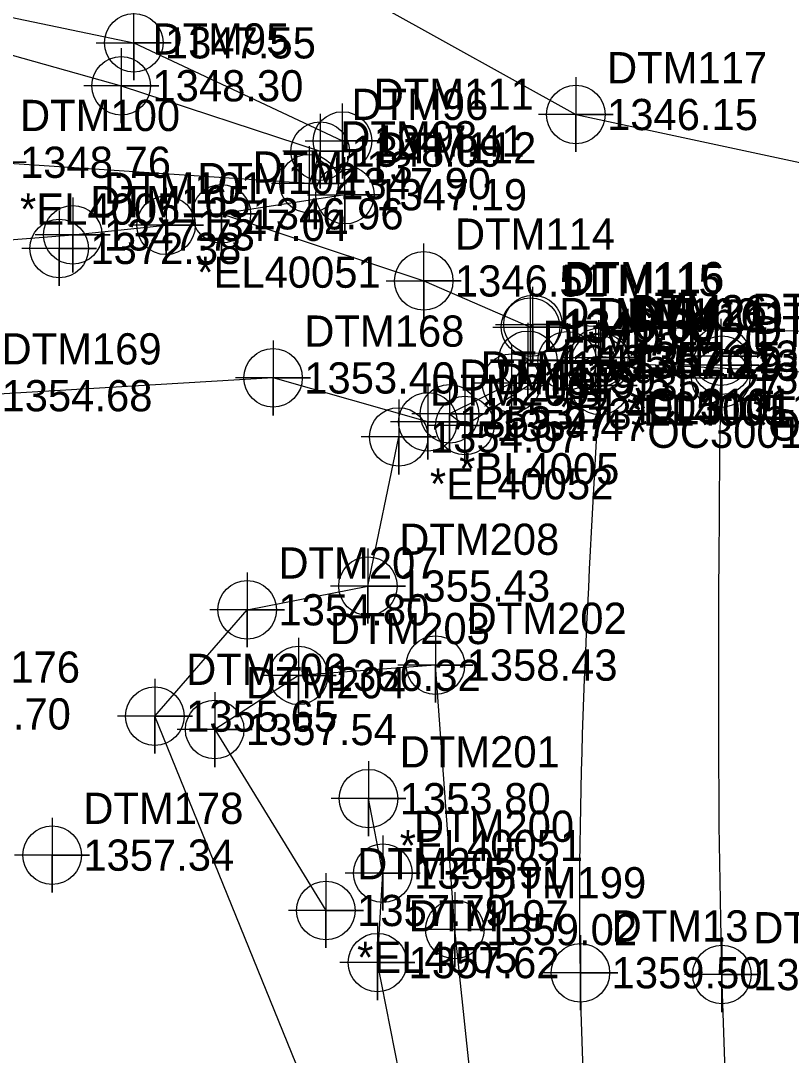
# Model space of a CAD drawing. Extents: x 1251905 to 1252853, y 859795 to 860170.
# Drawn here: x 1251978.6 to 1252040.3, y 859945.7 to 860028.5 of the extents above; entities that cross this region are included whole.
import ezdxf

# ---------------------------------------------------------------- set-up
doc = ezdxf.new("R2010")
doc.units = 0
for name, color, linetype in [('Exist DTM Breakline', 7, 'Continuous'), ('Exist DTM Breakline Cogo Comment', 7, 'Continuous'), ('Exist DTM Breakline Cogo Elevation', 7, 'Continuous'), ('Exist DTM Breakline Cogo Number', 7, 'Continuous'), ('Exist DTM Breakline Cogo Point CELL', 7, 'Continuous'), ('Exist DTM Breakline Underwater', 7, 'Continuous'), ('Exist DTM Breakline Underwater Cogo Elevation', 7, 'Continuous'), ('Exist DTM Breakline Underwater Cogo Number', 7, 'Continuous'), ('Exist DTM Breakline Underwater Cogo Point CELL', 7, 'Continuous'), ('Exist DTM Crownline', 7, 'Continuous'), ('Exist DTM Crownline Cogo Comment', 7, 'Continuous'), ('Exist DTM Crownline Cogo Elevation', 7, 'Continuous'), ('Exist DTM Crownline Cogo Number', 7, 'Continuous'), ('Exist DTM Crownline Cogo Point CELL', 7, 'Continuous'), ('Exist DTM Regular Point CELL', 7, 'Continuous'), ('Exist DTM Regular Point Cogo Elevation', 7, 'Continuous'), ('Exist DTM Regular Point Cogo Number', 7, 'Continuous'), ('Exist Hydro Stream or Body of Water', 7, 'Continuous'), ('Exist Hydro Stream or Body of Water Cogo Elevation', 7, 'Continuous'), ('Exist Hydro Stream or Body of Water Cogo Number', 7, 'Continuous'), ('Exist Hydro Stream or Body of Water Cogo Point CELL', 7, 'Continuous'), ('Exist Roads EOP', 7, 'Continuous'), ('Exist Roads EOP Cogo Comment', 7, 'Continuous'), ('Exist Roads EOP Cogo Elevation', 7, 'Continuous'), ('Exist Roads EOP Cogo Number', 7, 'Continuous'), ('Exist Roads EOP Cogo Point CELL', 7, 'Continuous'), ('Exist Structure Major Deck Tunnel Box Culvert Cogo Comment', 7, 'Continuous'), ('Exist Structure Major Deck Tunnel Box Culvert Cogo Elevation', 7, 'Continuous'), ('Exist Structure Major Deck Tunnel Box Culvert Cogo Number', 7, 'Continuous'), ('Exist Structure Major Deck Tunnel Box Culvert Cogo Point CELL', 7, 'Continuous'), ('Exist Utilities Power UG Cable Cogo Elevation', 7, 'Continuous'), ('Exist Utilities Power UG Cable Cogo Number', 7, 'Continuous'), ('Exist Utilities Power UG Cable Cogo Point CELL', 7, 'Continuous')]:
    doc.layers.add(name, color=color, linetype=linetype)

msp = doc.modelspace()

# ---------------------------------------------------------------- linework, layer by layer
at = {"layer": 'Exist DTM Breakline'}
for points in [[(1251922.639, 860029.05), (1251957.547, 860031.512), (1251986.698, 860023.305), (1252002.628, 860018.068), (1252001.734, 860015.469), (1251976.094, 860017.179)], [(1251919.208, 860016.218), (1251952.017, 860008.928), (1251982.813, 860011.362), (1251990.283, 860012.128)], [(1252011.253, 859996.384), (1251998.853, 859999.907), (1251974.611, 859998.485), (1251951.238, 860003.66), (1251927.383, 860002.484), (1251907.913, 860010.701)], [(1252019.258, 860001.319), (1252017.94, 859999.494), (1252012.977, 859997.038), (1252014.204, 859996.093), (1252022.404, 860001.28), (1252024.677, 860001.074)], [(1252011.684, 859917.958), (1251989.391, 859972.821), (1251996.782, 859981.337), (1252006.454, 859983.238), (1252008.913, 859995.179)], [(1252032.55, 859801.96), (1252026.376, 859850.562), (1252019.584, 859901.847), (1252017.298, 859918.826), (1252013.415, 859955.727), (1252011.851, 859976.908), (1252000.895, 859976.087), (1251994.179, 859971.747), (1252003.085, 859957.255)], [(1252030.055, 859801.697), (1252023.898, 859850.26), (1252016.404, 859902.034), (1252014.144, 859917.861), (1252007.209, 859953.081), (1252007.638, 859960.249), (1252006.494, 859966.213)]]:
    msp.add_lwpolyline(points, dxfattribs=at)
at = {"layer": 'Exist DTM Breakline Cogo Point CELL'}
for points in [[(1251986.698, 860026.305), (1251986.698, 860020.305), (1251986.698, 860023.305), (1251989.698, 860023.305), (1251983.698, 860023.305)], [(1252002.628, 860021.068), (1252002.628, 860015.068), (1252002.628, 860018.068), (1252005.628, 860018.068), (1251999.628, 860018.068)], [(1251976.094, 860020.179), (1251976.094, 860014.179), (1251976.094, 860017.179), (1251979.094, 860017.179), (1251973.094, 860017.179)], [(1252001.734, 860018.469), (1252001.734, 860012.469), (1252001.734, 860015.469), (1252004.734, 860015.469), (1251998.734, 860015.469)], [(1251990.283, 860015.128), (1251990.283, 860009.128), (1251990.283, 860012.128), (1251993.283, 860012.128), (1251987.283, 860012.128)], [(1251982.813, 860014.362), (1251982.813, 860008.362), (1251982.813, 860011.362), (1251985.813, 860011.362), (1251979.813, 860011.362)], [(1252019.258, 860004.319), (1252019.258, 859998.319), (1252019.258, 860001.319), (1252022.258, 860001.319), (1252016.258, 860001.319)], [(1252022.404, 860004.28), (1252022.404, 859998.28), (1252022.404, 860001.28), (1252025.404, 860001.28), (1252019.404, 860001.28)], [(1252024.677, 860004.074), (1252024.677, 859998.074), (1252024.677, 860001.074), (1252027.677, 860001.074), (1252021.677, 860001.074)], [(1251998.853, 860002.907), (1251998.853, 859996.907), (1251998.853, 859999.907), (1252001.853, 859999.907), (1251995.853, 859999.907)], [(1252017.94, 860002.494), (1252017.94, 859996.494), (1252017.94, 859999.494), (1252020.94, 859999.494), (1252014.94, 859999.494)], [(1252011.253, 859999.384), (1252011.253, 859993.384), (1252011.253, 859996.384), (1252014.253, 859996.384), (1252008.253, 859996.384)], [(1252012.977, 860000.038), (1252012.977, 859994.038), (1252012.977, 859997.038), (1252015.977, 859997.038), (1252009.977, 859997.038)], [(1252014.204, 859999.093), (1252014.204, 859993.093), (1252014.204, 859996.093), (1252017.204, 859996.093), (1252011.204, 859996.093)], [(1252008.913, 859998.179), (1252008.913, 859992.179), (1252008.913, 859995.179), (1252011.913, 859995.179), (1252005.913, 859995.179)], [(1252006.454, 859986.238), (1252006.454, 859980.238), (1252006.454, 859983.238), (1252009.454, 859983.238), (1252003.454, 859983.238)], [(1251996.782, 859984.337), (1251996.782, 859978.337), (1251996.782, 859981.337), (1251999.782, 859981.337), (1251993.782, 859981.337)], [(1252011.851, 859979.908), (1252011.851, 859973.908), (1252011.851, 859976.908), (1252014.851, 859976.908), (1252008.851, 859976.908)], [(1252000.895, 859979.087), (1252000.895, 859973.087), (1252000.895, 859976.087), (1252003.895, 859976.087), (1251997.895, 859976.087)], [(1251989.391, 859975.821), (1251989.391, 859969.821), (1251989.391, 859972.821), (1251992.391, 859972.821), (1251986.391, 859972.821)], [(1251994.179, 859974.747), (1251994.179, 859968.747), (1251994.179, 859971.747), (1251997.179, 859971.747), (1251991.179, 859971.747)], [(1252006.494, 859969.213), (1252006.494, 859963.213), (1252006.494, 859966.213), (1252009.494, 859966.213), (1252003.494, 859966.213)], [(1252007.638, 859963.249), (1252007.638, 859957.249), (1252007.638, 859960.249), (1252010.638, 859960.249), (1252004.638, 859960.249)], [(1252003.085, 859960.255), (1252003.085, 859954.255), (1252003.085, 859957.255), (1252006.085, 859957.255), (1252000.085, 859957.255)], [(1252013.415, 859958.727), (1252013.415, 859952.727), (1252013.415, 859955.727), (1252016.415, 859955.727), (1252010.415, 859955.727)], [(1252007.209, 859956.081), (1252007.209, 859950.081), (1252007.209, 859953.081), (1252010.209, 859953.081), (1252004.209, 859953.081)]]:
    msp.add_lwpolyline(points, dxfattribs=at)
for centre in [(1251986.698, 860023.305), (1252002.628, 860018.068), (1252001.734, 860015.469), (1251990.283, 860012.128), (1251982.813, 860011.362), (1252019.258, 860001.319), (1252022.404, 860001.28), (1252024.677, 860001.074), (1251998.853, 859999.907), (1252017.94, 859999.494), (1252012.977, 859997.038), (1252011.253, 859996.384), (1252014.204, 859996.093), (1252008.913, 859995.179), (1252006.454, 859983.238), (1251996.782, 859981.337), (1252011.851, 859976.908), (1252000.895, 859976.087), (1251989.391, 859972.821), (1251994.179, 859971.747), (1252006.494, 859966.213), (1252007.638, 859960.249), (1252003.085, 859957.255), (1252013.415, 859955.727), (1252007.209, 859953.081)]:
    msp.add_circle(centre, 2.344, dxfattribs=at)
at = {"layer": 'Exist DTM Breakline Underwater'}
msp.add_lwpolyline([(1251927.42, 860049.663), (1251960.607, 860043.428), (1251991.544, 860038.543), (1252023.095, 860021.002), (1252051.108, 860015.006), (1252097.444, 860018.35), (1252136.124, 860025.415), (1252179.795, 860024.836), (1252209.042, 860015.729)], dxfattribs=at)
at = {"layer": 'Exist DTM Breakline Underwater Cogo Point CELL'}
msp.add_lwpolyline([(1252023.095, 860024.002), (1252023.095, 860018.002), (1252023.095, 860021.002), (1252026.095, 860021.002), (1252020.095, 860021.002)], dxfattribs=at)
msp.add_circle((1252023.095, 860021.002), 2.344, dxfattribs=at)
at = {"layer": 'Exist DTM Crownline'}
msp.add_line((1252034.696, 859999.877), (1252034.747, 860000.476), dxfattribs=at)
msp.add_spline([(1252046.752, 859804.377), (1252041.79, 859852.778), (1252037.509, 859902.564), (1252034.798, 859952.124), (1252034.696, 859999.877)], degree=3, dxfattribs=at)
at = {"layer": 'Exist DTM Crownline Cogo Point CELL'}
for points in [[(1252034.785, 860003.924), (1252034.785, 859997.924), (1252034.785, 860000.924), (1252037.785, 860000.924), (1252031.785, 860000.924)], [(1252034.696, 860002.877), (1252034.696, 859996.877), (1252034.696, 859999.877), (1252037.696, 859999.877), (1252031.696, 859999.877)], [(1252034.798, 859955.124), (1252034.798, 859949.124), (1252034.798, 859952.124), (1252037.798, 859952.124), (1252031.798, 859952.124)]]:
    msp.add_lwpolyline(points, dxfattribs=at)
for centre in [(1252034.785, 860000.924), (1252034.696, 859999.877), (1252034.798, 859952.124)]:
    msp.add_circle(centre, 2.344, dxfattribs=at)
at = {"layer": 'Exist DTM Regular Point CELL'}
for points in [[(1252034.708, 860004.651), (1252034.708, 859998.651), (1252034.708, 860001.651), (1252037.708, 860001.651), (1252031.708, 860001.651)], [(1251981.162, 859964.689), (1251981.162, 859958.689), (1251981.162, 859961.689), (1251984.162, 859961.689), (1251978.162, 859961.689)]]:
    msp.add_lwpolyline(points, dxfattribs=at)
for centre in [(1252034.708, 860001.651), (1251981.162, 859961.689)]:
    msp.add_circle(centre, 2.344, dxfattribs=at)
at = {"layer": 'Exist Hydro Stream or Body of Water'}
msp.add_lwpolyline([(1251923.519, 860032.492), (1251957.999, 860032.964), (1251987.699, 860026.743), (1252004.412, 860018.883), (1252004.612, 860014.582), (1251994.716, 860013.049), (1252010.915, 860007.676), (1252019.462, 860003.97), (1252019.665, 860004.195), (1252046.38, 860003.539), (1252090.782, 859996.797), (1252140.715, 860010.791), (1252179.759, 860006.581), (1252205.549, 860000.12)], dxfattribs=at)
at = {"layer": 'Exist Hydro Stream or Body of Water Cogo Point CELL'}
for points in [[(1251984.699, 860026.743), (1251990.699, 860026.743), (1251987.699, 860026.743), (1251987.699, 860023.743), (1251987.699, 860029.743)], [(1252001.412, 860018.883), (1252007.412, 860018.883), (1252004.412, 860018.883), (1252004.412, 860015.883), (1252004.412, 860021.883)], [(1252001.612, 860014.582), (1252007.612, 860014.582), (1252004.612, 860014.582), (1252004.612, 860011.582), (1252004.612, 860017.582)], [(1251991.716, 860013.049), (1251997.716, 860013.049), (1251994.716, 860013.049), (1251994.716, 860010.049), (1251994.716, 860016.049)], [(1252007.915, 860007.676), (1252013.915, 860007.676), (1252010.915, 860007.676), (1252010.915, 860004.676), (1252010.915, 860010.676)], [(1252016.462, 860003.97), (1252022.462, 860003.97), (1252019.462, 860003.97), (1252019.462, 860000.97), (1252019.462, 860006.97)], [(1252016.665, 860004.195), (1252022.665, 860004.195), (1252019.665, 860004.195), (1252019.665, 860001.195), (1252019.665, 860007.195)]]:
    msp.add_lwpolyline(points, dxfattribs=at)
for centre in [(1251987.699, 860026.743), (1252004.412, 860018.883), (1252004.612, 860014.582), (1251994.716, 860013.049), (1252010.915, 860007.676), (1252019.462, 860003.97), (1252019.665, 860004.195)]:
    msp.add_circle(centre, 2.344, dxfattribs=at)
at = {"layer": 'Exist Roads EOP'}
msp.add_line((1252025.019, 859999.306), (1252025.059, 860001.178), dxfattribs=at)
msp.add_lwpolyline([(1252025.059, 860001.178), (1252043.922, 860000.266)], dxfattribs=at)
msp.add_spline([(1252037.3, 859803.862), (1252031.99, 859851.603), (1252026.974, 859902.147), (1252023.461, 859952.269), (1252025.019, 859999.306)], degree=3, dxfattribs=at)
at = {"layer": 'Exist Roads EOP Cogo Point CELL'}
for points in [[(1252025.059, 860004.178), (1252025.059, 859998.178), (1252025.059, 860001.178), (1252028.059, 860001.178), (1252022.059, 860001.178)], [(1252025.019, 860002.306), (1252025.019, 859996.306), (1252025.019, 859999.306), (1252028.019, 859999.306), (1252022.019, 859999.306)], [(1252023.461, 859955.269), (1252023.461, 859949.269), (1252023.461, 859952.269), (1252026.461, 859952.269), (1252020.461, 859952.269)]]:
    msp.add_lwpolyline(points, dxfattribs=at)
for centre in [(1252025.059, 860001.178), (1252025.019, 859999.306), (1252023.461, 859952.269)]:
    msp.add_circle(centre, 2.344, dxfattribs=at)
at = {"layer": 'Exist Structure Major Deck Tunnel Box Culvert Cogo Point CELL'}
msp.add_lwpolyline([(1252021.949, 860001.546), (1252027.949, 860001.546), (1252024.949, 860001.546), (1252024.949, 860004.546), (1252024.949, 859998.546)], dxfattribs=at)
msp.add_circle((1252024.949, 860001.546), 2.344, dxfattribs=at)
at = {"layer": 'Exist Utilities Power UG Cable Cogo Point CELL'}
msp.add_lwpolyline([(1251981.728, 860013.279), (1251981.728, 860007.279), (1251981.728, 860010.279), (1251984.728, 860010.279), (1251978.728, 860010.279)], dxfattribs=at)
msp.add_circle((1251981.728, 860010.279), 2.344, dxfattribs=at)

# ---------------------------------------------------------------- texts
at = {"layer": 'Exist DTM Breakline Cogo Comment'}
for s, p in [('*EL4005', (1251978.594, 860012.179)), ('*EL40051', (1251992.783, 860007.128)), ('*BL4005', (1252021.758, 859996.319)), ('*EL4005', (1252027.177, 859996.074)), ('*BL4005', (1252013.753, 859991.384)), ('*EL40052', (1252011.413, 859990.179)), ('*EL40051', (1252008.994, 859961.213)), ('*EL4005', (1252005.585, 859952.255))]:
    msp.add_text(s, height=2.5, dxfattribs=at).set_placement(p)
at = {"layer": 'Exist DTM Breakline Cogo Elevation'}
for s, p in [('1348.30', (1251989.198, 860022.055)), ('1348.09', (1252005.128, 860016.818)), ('1348.76', (1251978.594, 860015.929)), ('1347.90', (1252004.234, 860014.219)), ('1347.04', (1251992.783, 860010.878)), ('1347.73', (1251985.313, 860010.112)), ('1347.91', (1252021.758, 860000.069)), ('1357.20', (1252024.904, 860000.03)), ('1357.27', (1252027.177, 859999.824)), ('1353.40', (1252001.353, 859998.657)), ('1349.51', (1252020.44, 859998.244)), ('1354.68', (1251977.111, 859997.235)), ('1353.97', (1252013.753, 859995.134)), ('1353.73', (1252015.477, 859995.788)), ('1354.47', (1252016.704, 859994.843)), ('1354.07', (1252011.413, 859993.929)), ('1355.43', (1252008.954, 859981.988)), ('1354.80', (1251999.282, 859980.087)), ('1358.43', (1252014.351, 859975.658)), ('1356.32', (1252003.395, 859974.837)), ('1355.65', (1251991.891, 859971.571)), ('1357.54', (1251996.679, 859970.497)), ('1353.80', (1252008.994, 859964.963)), ('1355.91', (1252010.138, 859958.999)), ('1357.79', (1252005.585, 859956.005)), ('1359.02', (1252015.915, 859954.477)), ('1357.62', (1252009.709, 859951.831))]:
    msp.add_text(s, height=2.5, dxfattribs=at).set_placement(p)
at = {"layer": 'Exist DTM Breakline Cogo Number'}
for s, p in [('DTM95', (1251989.198, 860025.805)), ('DTM96', (1252005.128, 860020.568)), ('DTM100', (1251978.594, 860019.679)), ('DTM98', (1252004.234, 860017.969)), ('DTM102', (1251992.783, 860014.628)), ('DTM101', (1251985.313, 860013.862)), ('DTM154', (1252021.758, 860003.819)), ('DTM160', (1252024.904, 860003.78)), ('DTM161', (1252027.177, 860003.574)), ('DTM168', (1252001.353, 860002.407)), ('DTM155', (1252020.44, 860001.994)), ('DTM169', (1251977.111, 860000.985)), ('DTM158', (1252015.477, 859999.538)), ('DTM167', (1252013.753, 859998.884)), ('DTM159', (1252016.704, 859998.593)), ('DTM209', (1252011.413, 859997.679)), ('DTM208', (1252008.954, 859985.738)), ('DTM207', (1251999.282, 859983.837)), ('DTM202', (1252014.351, 859979.408)), ('DTM203', (1252003.395, 859978.587)), ('DTM206', (1251991.891, 859975.321)), ('DTM204', (1251996.679, 859974.247)), ('DTM201', (1252008.994, 859968.713)), ('DTM200', (1252010.138, 859962.749)), ('DTM205', (1252005.585, 859959.755)), ('DTM199', (1252015.915, 859958.227)), ('DTM197', (1252009.709, 859955.581))]:
    msp.add_text(s, height=2.5, dxfattribs=at).set_placement(p)
at = {"layer": 'Exist DTM Breakline Underwater Cogo Elevation'}
msp.add_text('1346.15', height=2.5, dxfattribs=at).set_placement((1252025.595, 860019.752))
at = {"layer": 'Exist DTM Breakline Underwater Cogo Number'}
msp.add_text('DTM117', height=2.5, dxfattribs=at).set_placement((1252025.595, 860023.502))
at = {"layer": 'Exist DTM Crownline Cogo Comment'}
for s, p in [('*EL3008', (1252037.285, 859995.924)), ('*OC3008', (1252037.196, 859994.877))]:
    msp.add_text(s, height=2.5, dxfattribs=at).set_placement(p)
at = {"layer": 'Exist DTM Crownline Cogo Elevation'}
for s, p in [('1357.30', (1252037.285, 859999.674)), ('1357.33', (1252037.196, 859998.627)), ('1359.55', (1252037.298, 859950.874))]:
    msp.add_text(s, height=2.5, dxfattribs=at).set_placement(p)
at = {"layer": 'Exist DTM Crownline Cogo Number'}
for s, p in [('DTM19', (1252037.285, 860003.424)), ('DTM18', (1252037.196, 860002.377)), ('DTM14', (1252037.298, 859954.624))]:
    msp.add_text(s, height=2.5, dxfattribs=at).set_placement(p)
at = {"layer": 'Exist DTM Regular Point Cogo Elevation'}
for s, p in [('1357.30', (1252037.208, 860000.401)), ('1358.70', (1251970.579, 859971.749)), ('1357.34', (1251983.662, 859960.439))]:
    msp.add_text(s, height=2.5, dxfattribs=at).set_placement(p)
at = {"layer": 'Exist DTM Regular Point Cogo Number'}
for s, p in [('DTM22', (1252037.208, 860004.151)), ('DTM176', (1251970.579, 859975.499)), ('DTM178', (1251983.662, 859964.189))]:
    msp.add_text(s, height=2.5, dxfattribs=at).set_placement(p)
at = {"layer": 'Exist Hydro Stream or Body of Water Cogo Elevation'}
for s, p in [('1347.55', (1251990.199, 860025.493)), ('1347.41', (1252006.912, 860017.633)), ('1347.19', (1252007.112, 860013.332)), ('1346.96', (1251997.216, 860011.799)), ('1346.51', (1252013.415, 860006.426)), ('1346.60', (1252021.962, 860002.72)), ('1346.60', (1252022.165, 860002.945))]:
    msp.add_text(s, height=2.5, dxfattribs=at).set_placement(p)
at = {"layer": 'Exist Hydro Stream or Body of Water Cogo Number'}
for s, p in [('DTM111', (1252006.912, 860021.383)), ('DTM112', (1252007.112, 860017.082)), ('DTM113', (1251997.216, 860015.549)), ('DTM114', (1252013.415, 860010.176)), ('DTM115', (1252021.962, 860006.47)), ('DTM116', (1252022.165, 860006.695))]:
    msp.add_text(s, height=2.5, dxfattribs=at).set_placement(p)
at = {"layer": 'Exist Roads EOP Cogo Comment'}
for s, p in [('*EL30011', (1252027.559, 859996.178)), ('*OC30011', (1252027.519, 859994.306))]:
    msp.add_text(s, height=2.5, dxfattribs=at).set_placement(p)
at = {"layer": 'Exist Roads EOP Cogo Elevation'}
for s, p in [('1357.19', (1252027.559, 859999.928)), ('1357.27', (1252027.519, 859998.056)), ('1359.50', (1252025.961, 859951.019))]:
    msp.add_text(s, height=2.5, dxfattribs=at).set_placement(p)
at = {"layer": 'Exist Roads EOP Cogo Number'}
for s, p in [('DTM21', (1252027.559, 860003.678)), ('DTM20', (1252027.519, 860001.806)), ('DTM13', (1252025.961, 859954.769))]:
    msp.add_text(s, height=2.5, dxfattribs=at).set_placement(p)
at = {"layer": 'Exist Structure Major Deck Tunnel Box Culvert Cogo Comment'}
msp.add_text('*CL3101', height=2.5, dxfattribs=at).set_placement((1252027.449, 859996.546))
at = {"layer": 'Exist Structure Major Deck Tunnel Box Culvert Cogo Elevation'}
msp.add_text('1357.15', height=2.5, dxfattribs=at).set_placement((1252027.449, 860000.296))
at = {"layer": 'Exist Structure Major Deck Tunnel Box Culvert Cogo Number'}
msp.add_text('DTM26', height=2.5, dxfattribs=at).set_placement((1252027.449, 860004.046))
at = {"layer": 'Exist Utilities Power UG Cable Cogo Elevation'}
msp.add_text('1372.38', height=2.5, dxfattribs=at).set_placement((1251984.228, 860009.029))
at = {"layer": 'Exist Utilities Power UG Cable Cogo Number'}
msp.add_text('DTM165', height=2.5, dxfattribs=at).set_placement((1251984.228, 860012.779))

doc.saveas('drawing.dxf')
